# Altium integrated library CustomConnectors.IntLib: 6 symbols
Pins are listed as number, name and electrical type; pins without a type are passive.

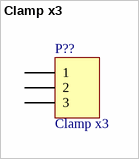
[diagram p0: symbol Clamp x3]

## Clamp x3
designator P??
footprint Connector x3 clamps
pins: 1, 2, 3


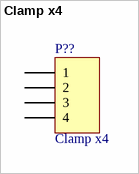
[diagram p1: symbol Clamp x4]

## Clamp x4
designator P??
footprint Connector Clamp (x4)
pins: 1, 2, 3, 4


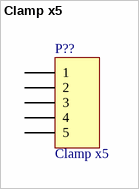
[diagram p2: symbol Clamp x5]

## Clamp x5
designator P??
footprint Connector Clamp (x5)
pins: 1, 2, 3, 4, 5


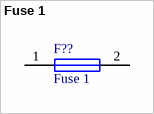
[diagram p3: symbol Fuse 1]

## Fuse 1
designator F??
Fuse
footprint Fuse Case
pins: 1, 2


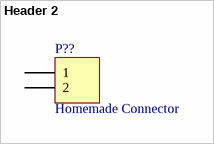
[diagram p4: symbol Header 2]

## Header 2
designator P??, comment Homemade Connector
Klema
footprint Connector (Clamp?)
pins: 1, 2


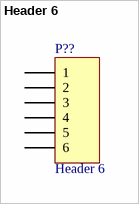
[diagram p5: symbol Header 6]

## Header 6
designator P??
Header, 6-Pin
footprint Connector Clamp (x6)
pins: 1, 2, 3, 4, 5, 6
